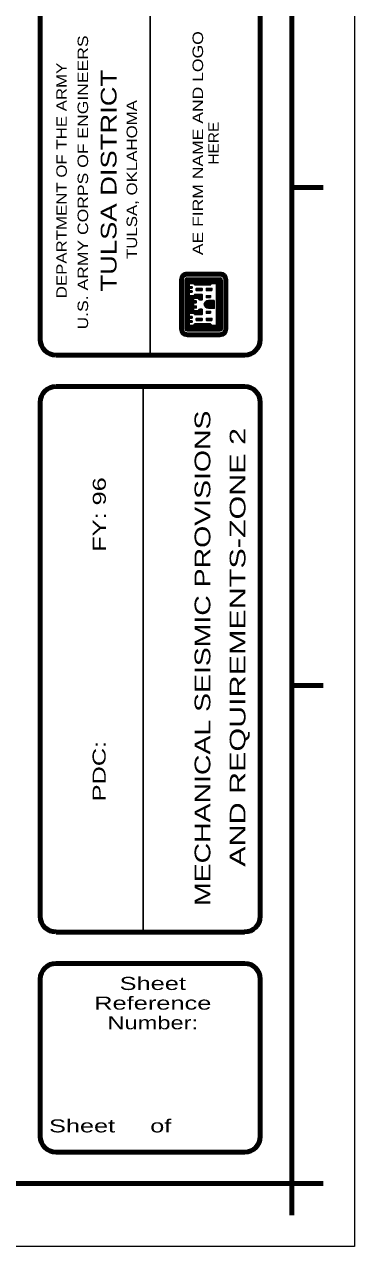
# Model space of a CAD drawing. Extents: x 55 to 190, y 198 to 264.
# Drawn here: x 140.29 to 146.59, y 198.45 to 221.76 of the extents above; entities that cross this region are included whole.
import ezdxf
from ezdxf.enums import TextEntityAlignment as Align

# ---------------------------------------------------------------- set-up
doc = ezdxf.new("R2010")
doc.units = 0
doc.header["$LTSCALE"] = 0.1
for name, color, linetype, lineweight in [('1', 7, 'Continuous', 25), ('3', 7, 'Continuous', 25), ('6', 7, 'Continuous', 25)]:
    doc.layers.add(name, color=color, linetype=linetype, lineweight=lineweight)

msp = doc.modelspace()

# ---------------------------------------------------------------- linework, layer by layer
at = {"layer": '1'}
for p, q in [((142.6927, 231.855), (142.6927, 215.4537)), ((142.559, 204.4512), (142.559, 214.8537))]:
    msp.add_line(p, q, dxfattribs=at)
at = {"layer": '1', "lineweight": 80}
for p, q in [((140.5927, 231.555), (140.5927, 215.7537)), ((144.7927, 215.7537), (144.7927, 231.555)), ((145.9927, 218.6512), (145.3927, 218.6512)), ((140.8927, 215.4537), (144.4927, 215.4537)), ((144.4927, 214.8537), (140.8927, 214.8537)), ((140.5927, 214.5537), (140.5927, 204.7512)), ((144.7927, 204.7512), (144.7927, 214.5537)), ((145.9927, 209.1512), (145.3927, 209.1512)), ((140.8927, 204.4512), (144.4927, 204.4512)), ((140.8927, 203.8512), (144.4927, 203.8512)), ((140.5927, 200.5512), (140.5927, 203.5512)), ((144.7927, 203.5512), (144.7927, 200.5512)), ((144.4927, 200.2512), (140.8927, 200.2512)), ((145.3927, 199.6512), (145.3927, 199.0512)), ((145.9927, 199.6512), (145.3927, 199.6512))]:
    msp.add_line(p, q, dxfattribs=at)
at = {"layer": '1', "lineweight": 13}
msp.add_lwpolyline([(62.4915, 257.8525), (146.5927, 257.8525), (146.5927, 198.4512), (62.4915, 198.4512)], close=True, dxfattribs=at)
at = {"layer": '1', "lineweight": 80}
msp.add_lwpolyline([(65.1915, 256.6525), (145.3927, 256.6525), (145.3927, 199.6512), (65.1915, 199.6512)], close=True, dxfattribs=at)
for centre, start, end in [((140.8922, 215.7538), 180, 270), ((144.4922, 215.7538), 270, 0), ((140.8922, 214.5538), 90, 180), ((144.4922, 214.5538), 0, 90), ((140.8922, 204.7517), 180, 270), ((144.4922, 204.7517), 270, 0), ((140.8925, 203.5517), 90, 180), ((144.4925, 203.5517), 0, 90), ((140.8925, 200.5517), 180, 270), ((144.4925, 200.5517), 270, 0)]:
    msp.add_arc(centre, 0.3, start, end, dxfattribs=at)
at = {"layer": '6'}
for p, q in [((144.0552, 217.0287), (143.3652, 217.0287)), ((144.0277, 217.0325), (143.394, 217.0325)), ((143.2565, 215.9525), (143.2565, 216.89)), ((143.3252, 216.9212), (143.2577, 216.9212)), ((143.3202, 216.9037), (143.2577, 216.9037)), ((143.3202, 216.8862), (143.2577, 216.8862)), ((143.3202, 216.8687), (143.2577, 216.8687)), ((143.3202, 216.85), (143.2577, 216.85)), ((143.3202, 216.8337), (143.2577, 216.8337)), ((143.3202, 216.815), (143.2577, 216.815)), ((143.3202, 216.7975), (143.2577, 216.7975)), ((143.3377, 216.94), (143.264, 216.94)), ((143.3565, 216.9562), (143.2715, 216.9562)), ((144.139, 216.975), (143.2827, 216.975)), ((144.1227, 216.9937), (143.3015, 216.9937)), ((144.1002, 217.0112), (143.3202, 217.0112)), ((143.3202, 215.9475), (143.3202, 216.895)), ((143.3602, 215.9525), (143.3602, 216.89)), ((144.0627, 216.8862), (143.3602, 216.8862)), ((144.0627, 216.8687), (143.3602, 216.8687)), ((144.0627, 216.85), (143.3602, 216.85)), ((144.0627, 216.8337), (143.3602, 216.8337)), ((143.4377, 216.815), (143.3602, 216.815)), ((143.4377, 216.7975), (143.3602, 216.7975)), ((144.0602, 216.9037), (143.3627, 216.9037)), ((144.0452, 216.9212), (143.3777, 216.9212)), ((144.0315, 216.965), (143.3915, 216.965)), ((144.0277, 216.925), (143.394, 216.925)), ((143.8627, 216.815), (143.5202, 216.815)), ((143.8465, 216.7975), (143.5377, 216.7975)), ((144.0627, 216.815), (143.9577, 216.815)), ((144.0627, 216.7975), (143.9577, 216.7975)), ((144.0627, 215.9475), (144.0627, 216.8862)), ((144.1502, 216.9562), (144.0652, 216.9562)), ((144.159, 216.94), (144.0852, 216.94)), ((144.164, 216.9212), (144.0965, 216.9212)), ((144.1652, 216.9037), (144.1002, 216.9037)), ((144.1002, 215.9475), (144.1002, 216.895)), ((144.1652, 216.8862), (144.1002, 216.8862)), ((144.1652, 216.8687), (144.1002, 216.8687)), ((144.1652, 216.85), (144.1002, 216.85)), ((144.1652, 216.8337), (144.1002, 216.8337)), ((144.1652, 216.815), (144.1002, 216.815)), ((144.1652, 216.7975), (144.1002, 216.7975)), ((144.1665, 215.9525), (144.1665, 216.89)), ((143.3202, 216.78), (143.2577, 216.78)), ((143.3202, 216.7625), (143.2577, 216.7625)), ((143.3202, 216.7437), (143.2577, 216.7437)), ((143.3202, 216.7275), (143.2577, 216.7275)), ((143.3202, 216.7087), (143.2577, 216.7087)), ((143.3202, 216.6912), (143.2577, 216.6912)), ((143.3202, 216.6737), (143.2577, 216.6737)), ((143.3202, 216.6562), (143.2577, 216.6562)), ((143.3202, 216.6375), (143.2577, 216.6375)), ((143.3202, 216.6212), (143.2577, 216.6212)), ((143.3202, 216.6025), (143.2577, 216.6025)), ((143.3202, 216.585), (143.2577, 216.585)), ((143.3202, 216.5675), (143.2577, 216.5675)), ((143.4377, 216.78), (143.3602, 216.78)), ((143.4377, 216.7625), (143.3602, 216.7625)), ((143.4902, 216.7437), (143.3602, 216.7437)), ((143.4377, 216.7275), (143.3602, 216.7275)), ((143.4377, 216.71), (143.3602, 216.71)), ((143.4377, 216.6912), (143.3602, 216.6912)), ((143.4902, 216.6737), (143.3602, 216.6737)), ((143.4902, 216.6562), (143.3602, 216.6562)), ((143.4377, 216.6375), (143.3602, 216.6375)), ((143.4377, 216.6212), (143.3602, 216.6212)), ((143.4377, 216.6025), (143.3602, 216.6025)), ((143.6802, 216.585), (143.3602, 216.585)), ((143.6802, 216.5675), (143.3602, 216.5675)), ((143.4377, 216.68), (143.4377, 216.7337)), ((143.6802, 216.6037), (143.5315, 216.6037)), ((143.6802, 216.7087), (143.569, 216.7087)), ((143.6802, 216.6912), (143.569, 216.6912)), ((143.869, 216.7087), (143.764, 216.7087)), ((143.869, 216.6912), (143.764, 216.6912)), ((143.8427, 216.585), (143.764, 216.585)), ((143.8427, 216.5675), (143.764, 216.5675)), ((144.0627, 216.78), (143.9577, 216.78)), ((144.0627, 216.7625), (143.9577, 216.7625)), ((144.0627, 216.7437), (143.9577, 216.7437)), ((144.0627, 216.7275), (143.9577, 216.7275)), ((144.0627, 216.7087), (143.9577, 216.7087)), ((144.0627, 216.6912), (143.9577, 216.6912)), ((144.0627, 216.6737), (143.9577, 216.6737)), ((144.0627, 216.6562), (143.9577, 216.6562)), ((144.0627, 216.6375), (143.9577, 216.6375)), ((144.0627, 216.6212), (143.9577, 216.6212)), ((144.0627, 216.6025), (143.9577, 216.6025)), ((144.0627, 216.585), (143.9577, 216.585)), ((144.0627, 216.5675), (143.9577, 216.5675)), ((144.1652, 216.78), (144.1002, 216.78)), ((144.1652, 216.7625), (144.1002, 216.7625)), ((144.1652, 216.7437), (144.1002, 216.7437)), ((144.1652, 216.7275), (144.1002, 216.7275)), ((144.1652, 216.7087), (144.1002, 216.7087)), ((144.1652, 216.6912), (144.1002, 216.6912)), ((144.1652, 216.6737), (144.1002, 216.6737)), ((144.1652, 216.6562), (144.1002, 216.6562)), ((144.1652, 216.6375), (144.1002, 216.6375)), ((144.1652, 216.6212), (144.1002, 216.6212)), ((144.1652, 216.6025), (144.1002, 216.6025)), ((144.1652, 216.585), (144.1002, 216.585)), ((144.1652, 216.5675), (144.1002, 216.5675)), ((143.3202, 216.55), (143.2577, 216.55)), ((143.3202, 216.5312), (143.2577, 216.5312)), ((143.3202, 216.515), (143.2577, 216.515)), ((143.3202, 216.4962), (143.2577, 216.4962)), ((143.3202, 216.4787), (143.2577, 216.4787)), ((143.3202, 216.4612), (143.2577, 216.4612)), ((143.3202, 216.4437), (143.2577, 216.4437)), ((143.3202, 216.425), (143.2577, 216.425)), ((143.3202, 216.4087), (143.2577, 216.4087)), ((143.3202, 216.39), (143.2577, 216.39)), ((143.3202, 216.3725), (143.2577, 216.3725)), ((143.3202, 216.355), (143.2577, 216.355)), ((143.3202, 216.3375), (143.2577, 216.3375)), ((143.6802, 216.55), (143.3602, 216.55)), ((143.5152, 216.5312), (143.3602, 216.5312)), ((143.5152, 216.515), (143.3602, 216.515)), ((143.5152, 216.515), (143.3602, 216.515)), ((143.5152, 216.4962), (143.3602, 216.4962)), ((143.569, 216.4787), (143.3602, 216.4787)), ((143.569, 216.4612), (143.3602, 216.4612)), ((143.5152, 216.4437), (143.3602, 216.4437)), ((143.5152, 216.425), (143.3602, 216.425)), ((143.5152, 216.4087), (143.3602, 216.4087)), ((143.5152, 216.39), (143.3602, 216.39)), ((143.569, 216.3725), (143.3602, 216.3725)), ((143.5152, 216.355), (143.3602, 216.355)), ((143.5152, 216.3375), (143.3602, 216.3375)), ((143.6802, 216.5325), (143.614, 216.5325)), ((143.6802, 216.515), (143.6277, 216.515)), ((143.9127, 216.425), (143.724, 216.425)), ((143.9127, 216.4087), (143.7265, 216.4087)), ((143.9127, 216.4437), (143.7302, 216.4437)), ((143.9127, 216.39), (143.7352, 216.39)), ((143.9127, 216.4612), (143.7402, 216.4612)), ((143.9127, 216.3725), (143.749, 216.3725)), ((143.9127, 216.4787), (143.7565, 216.4787)), ((143.9127, 216.355), (143.7752, 216.355)), ((143.9127, 216.4962), (143.8027, 216.4962)), ((143.9127, 216.3487), (143.9127, 216.495)), ((144.0627, 216.55), (143.9577, 216.55)), ((144.0627, 216.5312), (143.9577, 216.5312)), ((144.0627, 216.515), (143.9577, 216.515)), ((144.0627, 216.4962), (143.9577, 216.4962)), ((144.0627, 216.4787), (143.9577, 216.4787)), ((144.0627, 216.4612), (143.9577, 216.4612)), ((144.0627, 216.4437), (143.9577, 216.4437)), ((144.0627, 216.425), (143.9577, 216.425)), ((144.0627, 216.4087), (143.9577, 216.4087)), ((144.0627, 216.39), (143.9577, 216.39)), ((144.0627, 216.3725), (143.9577, 216.3725)), ((144.0627, 216.355), (143.9577, 216.355)), ((144.0627, 216.3375), (143.9577, 216.3375)), ((144.1652, 216.55), (144.1002, 216.55)), ((144.1652, 216.5312), (144.1002, 216.5312)), ((144.1652, 216.515), (144.1002, 216.515)), ((144.1652, 216.4962), (144.1002, 216.4962)), ((144.1652, 216.4787), (144.1002, 216.4787)), ((144.1652, 216.4612), (144.1002, 216.4612)), ((144.1652, 216.4437), (144.1002, 216.4437)), ((144.1652, 216.425), (144.1002, 216.425)), ((144.1652, 216.4087), (144.1002, 216.4087)), ((144.1652, 216.39), (144.1002, 216.39)), ((144.1652, 216.3725), (144.1002, 216.3725)), ((144.1652, 216.355), (144.1002, 216.355)), ((144.1652, 216.3375), (144.1002, 216.3375)), ((143.3202, 216.3187), (143.2577, 216.3187)), ((143.3202, 216.3025), (143.2577, 216.3025)), ((143.3202, 216.2837), (143.2577, 216.2837)), ((143.3202, 216.2662), (143.2577, 216.2662)), ((143.3202, 216.2475), (143.2577, 216.2475)), ((143.3202, 216.2312), (143.2577, 216.2312)), ((143.3202, 216.2125), (143.2577, 216.2125)), ((143.3202, 216.195), (143.2577, 216.195)), ((143.3202, 216.1775), (143.2577, 216.1775)), ((143.3202, 216.16), (143.2577, 216.16)), ((143.3202, 216.1412), (143.2577, 216.1412)), ((143.3202, 216.125), (143.2577, 216.125)), ((143.3202, 216.1062), (143.2577, 216.1062)), ((143.5152, 216.3187), (143.3602, 216.3187)), ((143.5152, 216.3025), (143.3602, 216.3025)), ((143.6802, 216.2837), (143.3602, 216.2837)), ((143.6802, 216.2662), (143.3602, 216.2662)), ((143.4377, 216.2475), (143.3602, 216.2475)), ((143.4377, 216.2312), (143.3602, 216.2312)), ((143.4377, 216.2125), (143.3602, 216.2125)), ((143.4377, 216.195), (143.3602, 216.195)), ((143.489, 216.1775), (143.3602, 216.1775)), ((143.4377, 216.16), (143.3602, 216.16)), ((143.4377, 216.1412), (143.3602, 216.1412)), ((143.4377, 216.125), (143.3602, 216.125)), ((143.4902, 216.1062), (143.3602, 216.1062)), ((143.6802, 216.25), (143.5202, 216.25)), ((143.6802, 216.2312), (143.5377, 216.2312)), ((143.6802, 216.1412), (143.569, 216.1412)), ((143.6802, 216.125), (143.569, 216.125)), ((143.6802, 216.3025), (143.6077, 216.3025)), ((143.6802, 216.3187), (143.624, 216.3187)), ((143.8427, 216.2837), (143.764, 216.2837)), ((143.8427, 216.2662), (143.764, 216.2662)), ((143.869, 216.1412), (143.764, 216.1412)), ((143.869, 216.125), (143.764, 216.125)), ((144.0627, 216.3187), (143.9577, 216.3187)), ((144.0627, 216.3025), (143.9577, 216.3025)), ((144.0627, 216.2837), (143.9577, 216.2837)), ((144.0627, 216.2662), (143.9577, 216.2662)), ((144.0627, 216.2475), (143.9577, 216.2475)), ((144.0627, 216.2312), (143.9577, 216.2312)), ((144.0627, 216.2125), (143.9577, 216.2125)), ((144.0627, 216.195), (143.9577, 216.195)), ((144.0627, 216.1775), (143.9577, 216.1775)), ((144.0627, 216.16), (143.9577, 216.16)), ((144.0627, 216.1412), (143.9577, 216.1412)), ((144.0627, 216.125), (143.9577, 216.125)), ((144.0627, 216.1062), (143.9577, 216.1062)), ((144.1652, 216.3187), (144.1002, 216.3187)), ((144.1652, 216.3025), (144.1002, 216.3025)), ((144.1652, 216.2837), (144.1002, 216.2837)), ((144.1652, 216.2662), (144.1002, 216.2662)), ((144.1652, 216.2475), (144.1002, 216.2475)), ((144.1652, 216.2312), (144.1002, 216.2312)), ((144.1652, 216.2125), (144.1002, 216.2125)), ((144.1652, 216.195), (144.1002, 216.195)), ((144.1652, 216.1775), (144.1002, 216.1775)), ((144.1652, 216.16), (144.1002, 216.16)), ((144.1652, 216.1412), (144.1002, 216.1412)), ((144.1652, 216.125), (144.1002, 216.125)), ((144.1652, 216.1062), (144.1002, 216.1062)), ((143.3202, 216.09), (143.2577, 216.09)), ((143.3202, 216.0712), (143.2577, 216.0712)), ((143.3202, 216.0537), (143.2577, 216.0537)), ((143.3202, 216.035), (143.2577, 216.035)), ((143.3202, 216.0187), (143.2577, 216.0187)), ((143.3202, 216), (143.2577, 216)), ((143.3202, 215.9825), (143.2577, 215.9825)), ((143.3202, 215.965), (143.2577, 215.965)), ((143.3202, 215.9475), (143.2577, 215.9475)), ((143.3252, 215.9287), (143.2577, 215.9287)), ((143.3302, 215.9125), (143.2602, 215.9125)), ((143.3452, 215.8937), (143.2677, 215.8937)), ((143.3915, 215.8762), (143.2765, 215.8762)), ((143.4902, 216.09), (143.3602, 216.09)), ((143.4377, 216.0712), (143.3602, 216.0712)), ((143.4377, 216.0537), (143.3602, 216.0537)), ((143.4377, 216.035), (143.3602, 216.035)), ((144.0627, 216.0187), (143.3602, 216.0187)), ((144.0627, 216), (143.3602, 216)), ((144.0627, 215.9825), (143.3602, 215.9825)), ((144.0627, 215.965), (143.3602, 215.965)), ((144.0627, 215.9475), (143.3602, 215.9475)), ((144.054, 215.9287), (143.3677, 215.9287)), ((144.0315, 215.8762), (143.3915, 215.8762)), ((144.0277, 215.9162), (143.394, 215.9162)), ((143.8577, 216.0375), (143.5277, 216.0375)), ((144.0627, 216.09), (143.9577, 216.09)), ((144.0627, 216.0712), (143.9577, 216.0712)), ((144.0627, 216.0537), (143.9577, 216.0537)), ((144.0627, 216.035), (143.9577, 216.035)), ((144.1452, 215.8762), (144.0315, 215.8762)), ((144.154, 215.8937), (144.0765, 215.8937)), ((144.1615, 215.9125), (144.0915, 215.9125)), ((144.1652, 215.9287), (144.099, 215.9287)), ((144.1652, 216.09), (144.1002, 216.09)), ((144.1652, 216.0712), (144.1002, 216.0712)), ((144.1652, 216.0537), (144.1002, 216.0537)), ((144.1652, 216.035), (144.1002, 216.035)), ((144.1652, 216.0187), (144.1002, 216.0187)), ((144.1652, 216), (144.1002, 216)), ((144.1652, 215.9825), (144.1002, 215.9825)), ((144.1652, 215.965), (144.1002, 215.965)), ((144.1652, 215.9475), (144.1002, 215.9475)), ((144.1327, 215.8587), (143.2902, 215.8587)), ((144.1152, 215.8412), (143.3065, 215.8412)), ((144.0852, 215.8225), (143.3377, 215.8225)), ((144.0277, 215.81), (143.394, 215.81))]:
    msp.add_line(p, q, dxfattribs=at)
for points in [[(143.4377, 216.7337), (143.4902, 216.7337), (143.4902, 216.76), (143.4377, 216.76), (143.4377, 216.8212), (143.5152, 216.8212), (143.5402, 216.7937), (143.8427, 216.7937), (143.869, 216.8212), (143.9577, 216.8212), (143.9577, 216.0225)], [(143.4902, 216.6537), (143.4902, 216.68), (143.4377, 216.68)], [(143.9577, 216.0225), (143.8727, 216.0225), (143.8427, 216.05), (143.5402, 216.05), (143.5152, 216.0225), (143.4377, 216.0225), (143.4377, 216.0825), (143.4902, 216.0825), (143.4902, 216.1087), (143.4377, 216.1087), (143.4377, 216.1625), (143.4902, 216.1625), (143.4902, 216.1887), (143.4377, 216.1887), (143.4377, 216.255), (143.5152, 216.255), (143.5402, 216.2287), (143.6802, 216.2287), (143.6802, 216.3287), (143.6327, 216.3287), (143.6077, 216.3025), (143.5152, 216.3025), (143.5152, 216.355), (143.569, 216.355), (143.569, 216.3887), (143.5152, 216.3887), (143.5152, 216.455), (143.569, 216.455), (143.569, 216.4875), (143.5152, 216.4875), (143.5152, 216.5412), (143.6077, 216.5412), (143.6327, 216.5075), (143.6802, 216.5075), (143.6802, 216.6137), (143.5402, 216.6137), (143.5152, 216.5887), (143.4377, 216.5887), (143.4377, 216.6537), (143.4902, 216.6537)], [(143.9577, 216.0225), (143.8727, 216.0225), (143.8427, 216.05), (143.5402, 216.05), (143.5152, 216.0225), (143.4377, 216.0225), (143.4377, 216.0825), (143.4902, 216.0825), (143.4902, 216.1087), (143.4377, 216.1087), (143.4377, 216.1625), (143.4902, 216.1625), (143.4902, 216.1887), (143.4377, 216.1887), (143.4377, 216.255), (143.5152, 216.255), (143.5402, 216.2287), (143.6802, 216.2287), (143.6802, 216.3287)], [(143.9127, 216.4962), (143.9127, 216.3487), (143.8027, 216.3487)]]:
    msp.add_lwpolyline(points, dxfattribs=at)
for points in [[(143.6802, 216.6875), (143.569, 216.6875), (143.569, 216.7275), (143.6802, 216.7275)], [(143.869, 216.6875), (143.764, 216.6875), (143.764, 216.7275), (143.869, 216.7275)], [(143.8427, 216.5537), (143.764, 216.5537), (143.764, 216.5887), (143.8427, 216.5887)], [(143.6802, 216.1162), (143.569, 216.1162), (143.569, 216.1562), (143.6802, 216.1562)], [(143.8427, 216.255), (143.764, 216.255), (143.764, 216.2887), (143.8427, 216.2887)], [(143.869, 216.1162), (143.764, 216.1162), (143.764, 216.1562), (143.869, 216.1562)]]:
    msp.add_lwpolyline(points, close=True, dxfattribs=at)
for centre, major_axis, start_param, end_param in [((143.3943, 216.8908), (0, -0.1417), 3.1415927, 4.712389), ((144.0277, 216.8908), (0, 0.1417), 4.712389, 6.2831853), ((143.3901, 216.8951), (0, -0.0709), 3.1415927, 4.712389), ((143.3943, 216.8908), (0, -0.0354), 3.1415927, 4.712389), ((144.0277, 216.8908), (0, 0.0354), 4.712389, 6.2831853), ((144.0319, 216.8951), (0, 0.0709), 4.712389, 6.2831853), ((143.8068, 216.4116), (0, -0.0858), 3.191454, 4.577619), ((143.8068, 216.4346), (0, -0.0858), 4.8471589, 6.2333239), ((143.3943, 215.9525), (0, -0.1417), 4.712389, 6.2831853), ((143.3901, 215.9483), (0, -0.0709), 4.712389, 6.2831853), ((143.3943, 215.9525), (0, -0.0354), 4.712389, 6.2831853), ((144.0277, 215.9525), (0, -0.1417), 6.2831853, 7.8539816), ((144.0277, 215.9525), (0, 0.0354), 3.1415927, 4.712389), ((144.0319, 215.9483), (0, 0.0709), 3.1415927, 4.712389)]:
    msp.add_ellipse(centre, major_axis=major_axis, ratio=0.9801, start_param=start_param, end_param=end_param, dxfattribs=at)

# ---------------------------------------------------------------- texts
at = {"layer": '1'}
for s, height, width, p in [('U.S. ARMY CORPS OF ENGINEERS', 0.2, 1.25, (141.5052, 218.7488)), ('AE FIRM NAME AND LOGO', 0.2, 1.25, (143.7002, 219.4975)), ('DEPARTMENT OF THE ARMY', 0.2, 1.2, (141.099, 218.7863)), ('TULSA DISTRICT', 0.3, 1.3, (142.0477, 218.7825)), ('TULSA, OKLAHOMA', 0.2, 1.2, (142.4402, 218.8038)), ('HERE', 0.2, 1.1, (144.0002, 219.4975)), ('FY: 96', 0.2488, 1.45, (141.844, 212.4144)), ('PDC:                ', 0.2488, 1.45, (141.8402, 208.5925))]:
    msp.add_text(s, height=height, rotation=90, dxfattribs=dict(at, width=width)).set_placement(p, align=Align.CENTER)
for s, width, p in [('Sheet', 1.45, (142.7402, 203.345)), ('Reference', 1.45, (142.7402, 202.97)), ('Number:', 1.35, (142.7402, 202.595))]:
    msp.add_text(s, height=0.25, dxfattribs=dict(at, width=width)).set_placement(p, align=Align.CENTER)
at = {"layer": '3'}
for s, width, p in [('  MECHANICAL SEISMIC PROVISIONS  ', 1.35, (143.839, 209.6725)), ('      AND REQUIREMENTS-ZONE 2    ', 1.45, (144.509, 209.7187))]:
    msp.add_text(s, height=0.3, rotation=90, dxfattribs=dict(at, width=width)).set_placement(p, align=Align.CENTER)
at = {"layer": '3', "width": 1.45}
msp.add_text('Sheet     of', height=0.2488, dxfattribs=at).set_placement((140.7602, 200.6287))
msp.add_text('Sheet     of', height=0.2488, dxfattribs=at).set_placement((140.7602, 200.6287))

doc.saveas('drawing.dxf')
